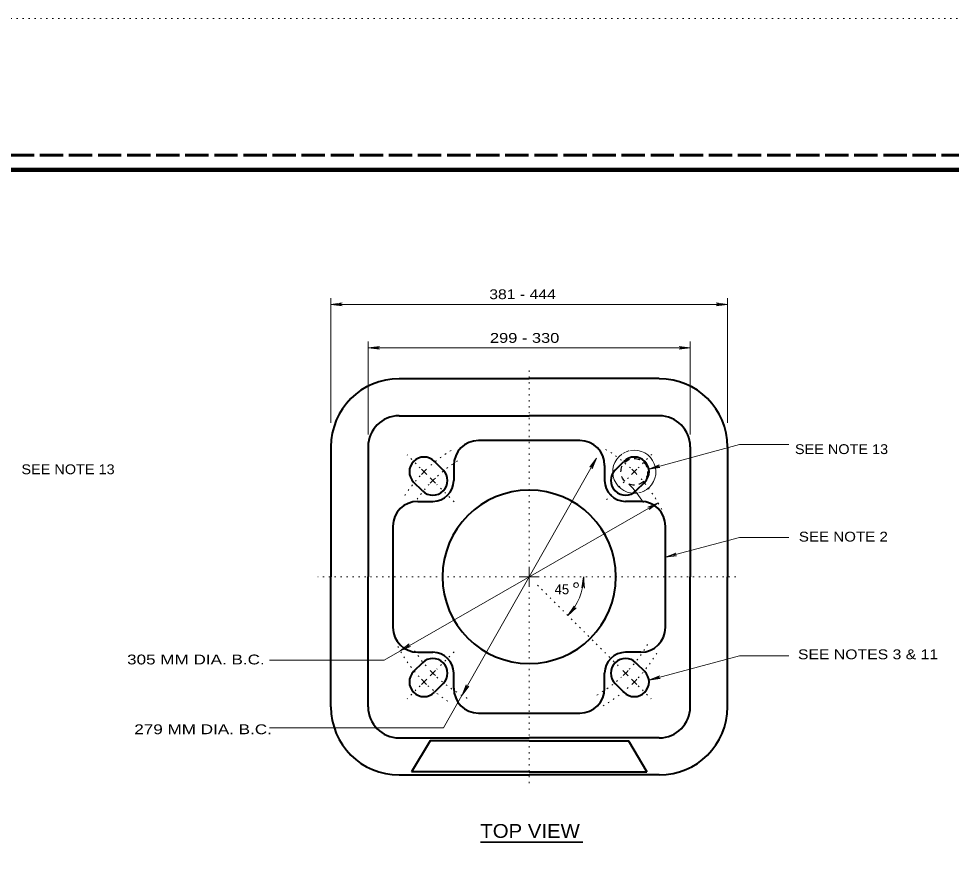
# Model space of a CAD drawing. Extents: x 312583 to 312854, y 144419 to 144597.
# Drawn here: x 312679.6 to 312751.7, y 144530.6 to 144596.8 of the extents above; entities that cross this region are included whole.
import ezdxf
from ezdxf.enums import TextEntityAlignment as Align

# ---------------------------------------------------------------- set-up
doc = ezdxf.new("R2010")
doc.units = 0
doc.header["$LTSCALE"] = 0.3
for name, pattern in [('DOTTED', [1.5, 0.3, -1.2]), ('LONG_DASHED', [7.5, 6, -1.5]), ('SHORT_DASHED', [2.7, 1.5, -1.2])]:
    doc.linetypes.add(name, pattern=pattern)
for name, color, linetype, lineweight in [('1', 7, 'Continuous', 40), ('2', 7, 'Continuous', 13), ('62', 7, 'DOTTED', 13), ('63', 7, 'LONG_DASHED', 60)]:
    doc.layers.add(name, color=color, linetype=linetype, lineweight=lineweight)

msp = doc.modelspace()

# ---------------------------------------------------------------- linework, layer by layer
at = {"layer": '1'}
for p, q in [((312708.9877, 144568.9263), (312719.054, 144568.9263)), ((312729.1127, 144568.9263), (312719.054, 144568.9263)), ((312708.9877, 144566.0513), (312719.054, 144566.0513)), ((312729.1127, 144566.0513), (312719.054, 144566.0513)), ((312719.054, 144564.1346), (312715.1287, 144564.1346)), ((312722.9717, 144564.1346), (312719.054, 144564.1346)), ((312703.7207, 144563.6516), (312703.7207, 144553.5929)), ((312706.5957, 144563.6516), (312706.5957, 144553.5929)), ((312731.5123, 144563.6516), (312731.5123, 144553.5929)), ((312734.3873, 144563.6516), (312734.3873, 144553.5929)), ((312712.3993, 144561.8499), (312711.7247, 144562.5246)), ((312725.701, 144561.8499), (312726.3757, 144562.5246)), ((312713.212, 144562.2179), (312713.212, 144561.0449)), ((312724.8883, 144562.2179), (312724.8883, 144561.0449)), ((312710.7893, 144560.2399), (312710.1147, 144560.9146)), ((312727.311, 144560.2399), (312727.9857, 144560.9146)), ((312710.429, 144559.4273), (312711.5943, 144559.4273)), ((312727.679, 144559.4273), (312726.506, 144559.4273)), ((312708.5123, 144557.5106), (312708.5123, 144553.5929)), ((312729.5957, 144553.5929), (312729.5957, 144557.5106)), ((312703.7207, 144543.5266), (312703.7207, 144553.5929)), ((312706.5957, 144543.5266), (312706.5957, 144553.5929)), ((312708.5123, 144553.5929), (312708.5123, 144549.6753)), ((312729.5957, 144549.6753), (312729.5957, 144553.5929)), ((312731.5123, 144543.5266), (312731.5123, 144553.5929)), ((312734.3873, 144543.5266), (312734.3873, 144553.5929)), ((312710.429, 144547.7586), (312711.5943, 144547.7586)), ((312727.679, 144547.7586), (312726.506, 144547.7586)), ((312710.7893, 144546.9459), (312710.1147, 144546.2636)), ((312727.311, 144546.9459), (312727.9857, 144546.2636)), ((312713.212, 144544.9679), (312713.212, 144546.1409)), ((312724.8883, 144544.9679), (312724.8883, 144546.1409)), ((312712.3993, 144545.3359), (312711.7247, 144544.6536)), ((312725.701, 144545.3359), (312726.3757, 144544.6536)), ((312715.1287, 144543.0513), (312719.054, 144543.0513)), ((312719.054, 144543.0513), (312722.9717, 144543.0513)), ((312708.9877, 144541.1346), (312719.054, 144541.1346)), ((312729.1127, 144541.1346), (312719.054, 144541.1346)), ((312708.9877, 144538.2596), (312719.054, 144538.2596)), ((312719.054, 144538.4973), (312709.946, 144538.4973)), ((312719.054, 144538.4973), (312728.1543, 144538.4973)), ((312729.1127, 144538.2596), (312719.054, 144538.2596))]:
    msp.add_line(p, q, dxfattribs=at)
at = {"layer": '1', "linetype": 'DOTTED', "lineweight": 13}
for p, q in [((312727.4797, 144562.0186), (312728.6297, 144563.1686)), ((312710.6207, 144562.0186), (312709.624, 144563.0229)), ((312725.0263, 144559.5653), (312726.7743, 144561.3133)), ((312713.2427, 144559.4043), (312711.9087, 144560.7306)), ((312719.6903, 144552.9489), (312726.1917, 144546.4476)), ((312713.2427, 144547.7816), (312711.9087, 144546.4476)), ((312710.6207, 144545.1596), (312709.624, 144544.1629)), ((312727.4797, 144545.1596), (312728.4763, 144544.1629))]:
    msp.add_line(p, q, dxfattribs=at)
at = {"layer": '1', "lineweight": 13}
for p, q in [((312711.1267, 144561.5126), (312710.7203, 144561.9189)), ((312726.9737, 144561.5126), (312727.38, 144561.9189)), ((312711.8013, 144560.8456), (312711.395, 144561.2519)), ((312711.8013, 144546.3403), (312711.395, 144545.9339)), ((312726.3067, 144546.3403), (312726.713, 144545.9339)), ((312711.1267, 144545.6733), (312710.7203, 144545.2669)), ((312726.9737, 144545.6733), (312727.38, 144545.2669))]:
    msp.add_line(p, q, dxfattribs=at)
at = {"layer": '1', "lineweight": 158}
msp.add_lwpolyline([(312616.5, 144423.1446), (312616.5, 144585.0846), (312849, 144585.0846)], dxfattribs=at)
at = {"layer": '1'}
for points in [[(312719.054, 144540.8969), (312711.3873, 144540.8969), (312709.946, 144538.4973)], [(312719.054, 144540.8969), (312726.7207, 144540.8969), (312728.1543, 144538.4973)]]:
    msp.add_lwpolyline(points, dxfattribs=at)
at = {"layer": '1', "linetype": 'SHORT_DASHED', "lineweight": 25}
msp.add_circle((312727.1807, 144561.7215), 1.0339, dxfattribs=at)
at = {"layer": '1'}
for centre, radius, start, end in [((312708.9877, 144563.6535), 5.2708, 90, 180), ((312729.1127, 144563.6535), 5.2708, 0, 90), ((312708.9877, 144563.6535), 2.3958, 90, 180), ((312729.1127, 144563.6535), 2.3958, 0, 90), ((312715.1306, 144562.216), 1.9167, 90, 180), ((312722.9697, 144562.216), 1.9167, 0, 90), ((312710.9197, 144561.7215), 1.1384, 45, 225), ((312727.1807, 144561.7215), 1.1384, 315, 135), ((312711.5963, 144561.0449), 1.1384, 225, 45), ((312726.5041, 144561.0449), 1.1384, 135, 315), ((312711.5963, 144561.0449), 1.6176, 270, 0), ((312726.5041, 144561.0449), 1.6176, 180, 270), ((312719.0502, 144553.591), 6.7083, 90, 180), ((312719.0502, 144553.591), 6.7083, 0, 90), ((312710.4252, 144557.5106), 1.9167, 90, 180), ((312727.6752, 144557.5106), 1.9167, 0, 90), ((312719.0502, 144553.591), 6.7083, 180, 270), ((312719.0502, 144553.591), 6.7083, 270, 0), ((312710.4252, 144549.6714), 1.9167, 180, 270), ((312727.6752, 144549.6714), 1.9167, 270, 0), ((312711.5963, 144546.1371), 1.1384, 315, 135), ((312711.5963, 144546.1371), 1.6176, 0, 90), ((312726.5041, 144546.1371), 1.6176, 90, 180), ((312726.5041, 144546.1371), 1.1384, 45, 225), ((312710.9197, 144545.4605), 1.1384, 135, 315), ((312727.1807, 144545.4605), 1.1384, 225, 45), ((312715.1306, 144544.966), 1.9167, 180, 270), ((312722.9697, 144544.966), 1.9167, 270, 0), ((312708.9877, 144543.5285), 5.2708, 180, 270), ((312708.9877, 144543.5285), 2.3958, 180, 270), ((312729.1127, 144543.5285), 5.2708, 270, 0), ((312729.1127, 144543.5285), 2.3958, 270, 0)]:
    msp.add_arc(centre, radius, start, end, dxfattribs=at)
at = {"layer": '1', "linetype": 'DOTTED', "lineweight": 13}
for radius, start, end in [(11.5, 121.71451, 132.90639), (11.5, 47.09459, 60.18147), (10.5417, 121.71386, 132.58339), (11.5, 137.18158, 147.17965), (11.5, 26.95504, 42.81842), (10.5417, 137.23997, 147.17573), (11.5, 207.95114, 222.81842), (10.5417, 317.23939, 330.45291), (10.5417, 212.82427, 222.76003), (11.5, 317.18755, 330.45291), (10.5417, 227.41661, 243.86032), (10.5417, 299.81853, 312.58463), (11.5, 227.09361, 238.28549), (11.5, 299.81853, 312.90541)]:
    msp.add_arc((312719.0502, 144553.591), radius, start, end, dxfattribs=at)
at = {"layer": '1', "lineweight": 13}
for centre, radius, start, end in [((312727.1807, 144561.7215), 1.6684, 124.98128, 279.36449), ((312727.1807, 144561.7215), 1.6684, 114.18887, 121.95657), ((312727.1807, 144561.7215), 1.6684, 103.53942, 111.8503), ((312727.1807, 144561.7215), 1.6684, 303.24891, 100.41698), ((312719.0502, 144553.591), 11.5, 133.65585, 136.45218), ((312719.0502, 144553.591), 11.5, 43.54782, 46.34415), ((312719.0502, 144553.591), 10.5417, 133.51949, 136.65089), ((312719.0502, 144553.591), 10.5417, 33.10756, 42.76003), ((312727.1807, 144561.7215), 1.6684, 291.78903, 300.84898), ((312727.1807, 144561.7215), 1.6684, 282.10403, 289.21172), ((312719.0502, 144553.591), 10.5417, 223.34911, 226.48051), ((312719.0502, 144553.591), 10.5417, 313.51949, 316.65089), ((312719.0502, 144553.591), 11.5, 223.54782, 226.34415), ((312719.0502, 144553.591), 11.5, 313.65585, 316.45218)]:
    msp.add_arc(centre, radius, start, end, dxfattribs=at)
at = {"layer": '2'}
for p, q in [((312703.7207, 144565.5069), (312703.7207, 144575.1593)), ((312703.7207, 144574.6763), (312704.587, 144574.7836)), ((312703.7207, 144574.6763), (312734.3873, 144574.6763)), ((312703.7207, 144574.6763), (312704.587, 144574.5689)), ((312704.587, 144574.7836), (312704.311, 144574.6763)), ((312704.587, 144574.5689), (312704.311, 144574.6763)), ((312733.521, 144574.7836), (312733.797, 144574.6763)), ((312734.3873, 144574.6763), (312733.521, 144574.7836)), ((312733.521, 144574.5689), (312733.797, 144574.6763)), ((312734.3873, 144574.6763), (312733.521, 144574.5689)), ((312734.3873, 144565.5069), (312734.3873, 144575.1593)), ((312706.5957, 144564.6099), (312706.5957, 144571.8013)), ((312731.5123, 144564.6099), (312731.5123, 144571.8013)), ((312706.5957, 144571.3183), (312707.462, 144571.4256)), ((312706.5957, 144571.3183), (312731.5123, 144571.3183)), ((312706.5957, 144571.3183), (312707.462, 144571.2109)), ((312707.462, 144571.4256), (312707.186, 144571.3183)), ((312707.462, 144571.2109), (312707.186, 144571.3183)), ((312730.646, 144571.4256), (312730.922, 144571.3183)), ((312731.5123, 144571.3183), (312730.646, 144571.4256)), ((312730.646, 144571.2109), (312730.922, 144571.3183)), ((312731.5123, 144571.3183), (312730.646, 144571.2109)), ((312712.4223, 144541.8936), (312724.252, 144562.7623)), ((312724.252, 144562.7623), (312723.7307, 144562.0646)), ((312724.252, 144562.7623), (312723.9147, 144561.9573)), ((312723.7307, 144562.0646), (312723.9607, 144562.2486)), ((312723.9147, 144561.9573), (312723.9607, 144562.2486)), ((312728.3, 144561.9343), (312729.105, 144562.2639)), ((312728.3, 144561.9343), (312729.1663, 144562.0569)), ((312729.105, 144562.2639), (312728.8673, 144562.0876)), ((312729.1663, 144562.0569), (312728.8673, 144562.0876)), ((312729.0283, 144559.3123), (312707.8223, 144547.1529)), ((312729.0283, 144559.3123), (312728.2233, 144558.9749)), ((312728.2233, 144558.9749), (312728.5147, 144559.0209)), ((312729.0283, 144559.3123), (312728.3307, 144558.7909)), ((312728.3307, 144558.7909), (312728.5147, 144559.0209)), ((312729.5957, 144555.1033), (312730.4007, 144555.4329)), ((312729.5957, 144555.1033), (312730.4543, 144555.2259)), ((312730.4007, 144555.4329), (312730.163, 144555.2566)), ((312730.4543, 144555.2259), (312730.163, 144555.2566)), ((312719.054, 144553.5929), (312719.054, 144554.3596)), ((312719.054, 144553.5929), (312719.054, 144554.3596)), ((312719.054, 144553.5929), (312718.2873, 144553.5929)), ((312719.054, 144553.5929), (312719.8207, 144553.5929)), ((312719.054, 144553.5929), (312719.054, 144552.8263)), ((312723.263, 144553.5929), (312723.1173, 144552.7343)), ((312723.1173, 144552.7343), (312723.2323, 144553.0026)), ((312723.3243, 144552.7189), (312723.2323, 144553.0026)), ((312723.263, 144553.5929), (312723.3243, 144552.7189)), ((312722.0287, 144550.6106), (312722.5347, 144551.3236)), ((312722.0287, 144550.6106), (312722.688, 144551.1856)), ((312722.5347, 144551.3236), (312722.4273, 144551.0476)), ((312722.688, 144551.1856), (312722.4273, 144551.0476)), ((312709.072, 144547.8736), (312709.7697, 144548.3949)), ((312709.072, 144547.8736), (312709.877, 144548.2109)), ((312709.7697, 144548.3949), (312709.5857, 144548.1649)), ((312709.877, 144548.2109), (312709.5857, 144548.1649)), ((312707.8223, 144547.1529), (312698.9597, 144547.1529)), ((312728.3077, 144545.6043), (312729.1203, 144545.9263)), ((312729.1203, 144545.9263), (312728.8827, 144545.7576)), ((312713.856, 144544.4236), (312714.1857, 144545.2286)), ((312713.856, 144544.4236), (312714.3773, 144545.1213)), ((312714.1857, 144545.2286), (312714.1473, 144544.9373)), ((312714.3773, 144545.1213), (312714.1473, 144544.9373)), ((312728.3077, 144545.6043), (312729.174, 144545.7193)), ((312729.174, 144545.7193), (312728.8827, 144545.7576)), ((312712.4223, 144541.8936), (312698.9597, 144541.8936))]:
    msp.add_line(p, q, dxfattribs=at)
at = {"layer": '2', "linetype": 'DOTTED'}
for p, q in [((312719.054, 144554.7429), (312719.054, 144569.6776)), ((312717.904, 144553.5929), (312702.701, 144553.5929)), ((312720.204, 144553.5929), (312735.2077, 144553.5929)), ((312719.054, 144552.4429), (312719.054, 144537.4393))]:
    msp.add_line(p, q, dxfattribs=at)
at = {"layer": '2', "lineweight": 35}
msp.add_line((312715.2884, 144533.0693), (312723.2056, 144533.0693), dxfattribs=at)
at = {"layer": '2'}
for points in [[(312728.3, 144561.9343), (312735.3073, 144563.8203), (312739.1407, 144563.8203)], [(312729.5957, 144555.1033), (312735.3073, 144556.6366), (312739.1407, 144556.6366)], [(312728.3077, 144545.6043), (312735.3073, 144547.4826), (312739.1407, 144547.4826)]]:
    msp.add_lwpolyline(points, dxfattribs=at)
msp.add_circle((312722.6801, 144552.9508), 0.1797, dxfattribs=at)
msp.add_arc((312719.0502, 144553.591), 4.2148, 315, 0, dxfattribs=at)
at = {"layer": '62'}
msp.add_line((312601.2, 144596.7846), (312853.5, 144596.7846), dxfattribs=at)
at = {"layer": '63'}
msp.add_line((312851.75, 144586.2246), (312583.526, 144586.2246), dxfattribs=at)

# ---------------------------------------------------------------- texts
at = {"layer": '2'}
for s, width, p in [('381 - 444', 1.2, (312715.9599, 144575.078)), ('299 - 330', 1.25, (312716.0137, 144571.6981)), ('SEE NOTE 13', 1.1, (312739.6083, 144563.0909)), ('SEE NOTE 13', 1.1, (312679.7777, 144561.5339)), ('SEE NOTE 2', 1.15, (312739.9088, 144556.3206)), ('SEE NOTES 3 & 11', 1.2, (312739.8377, 144547.2149)), ('305 MM DIA. B.C.', 1.3, (312687.9484, 144546.8139)), ('279 MM DIA. B.C.', 1.3, (312688.5056, 144541.4143))]:
    msp.add_text(s, height=0.76, dxfattribs=dict(at, width=width)).set_placement(p)
msp.add_text('45', height=0.76, dxfattribs=at).set_placement((312721.0139, 144552.2454))
at = {"layer": '2', "width": 1.1}
msp.add_text('TOP VIEW', height=1.07, dxfattribs=at).set_placement((312719.1197, 144533.391), align=Align.CENTER)

doc.saveas('drawing.dxf')
